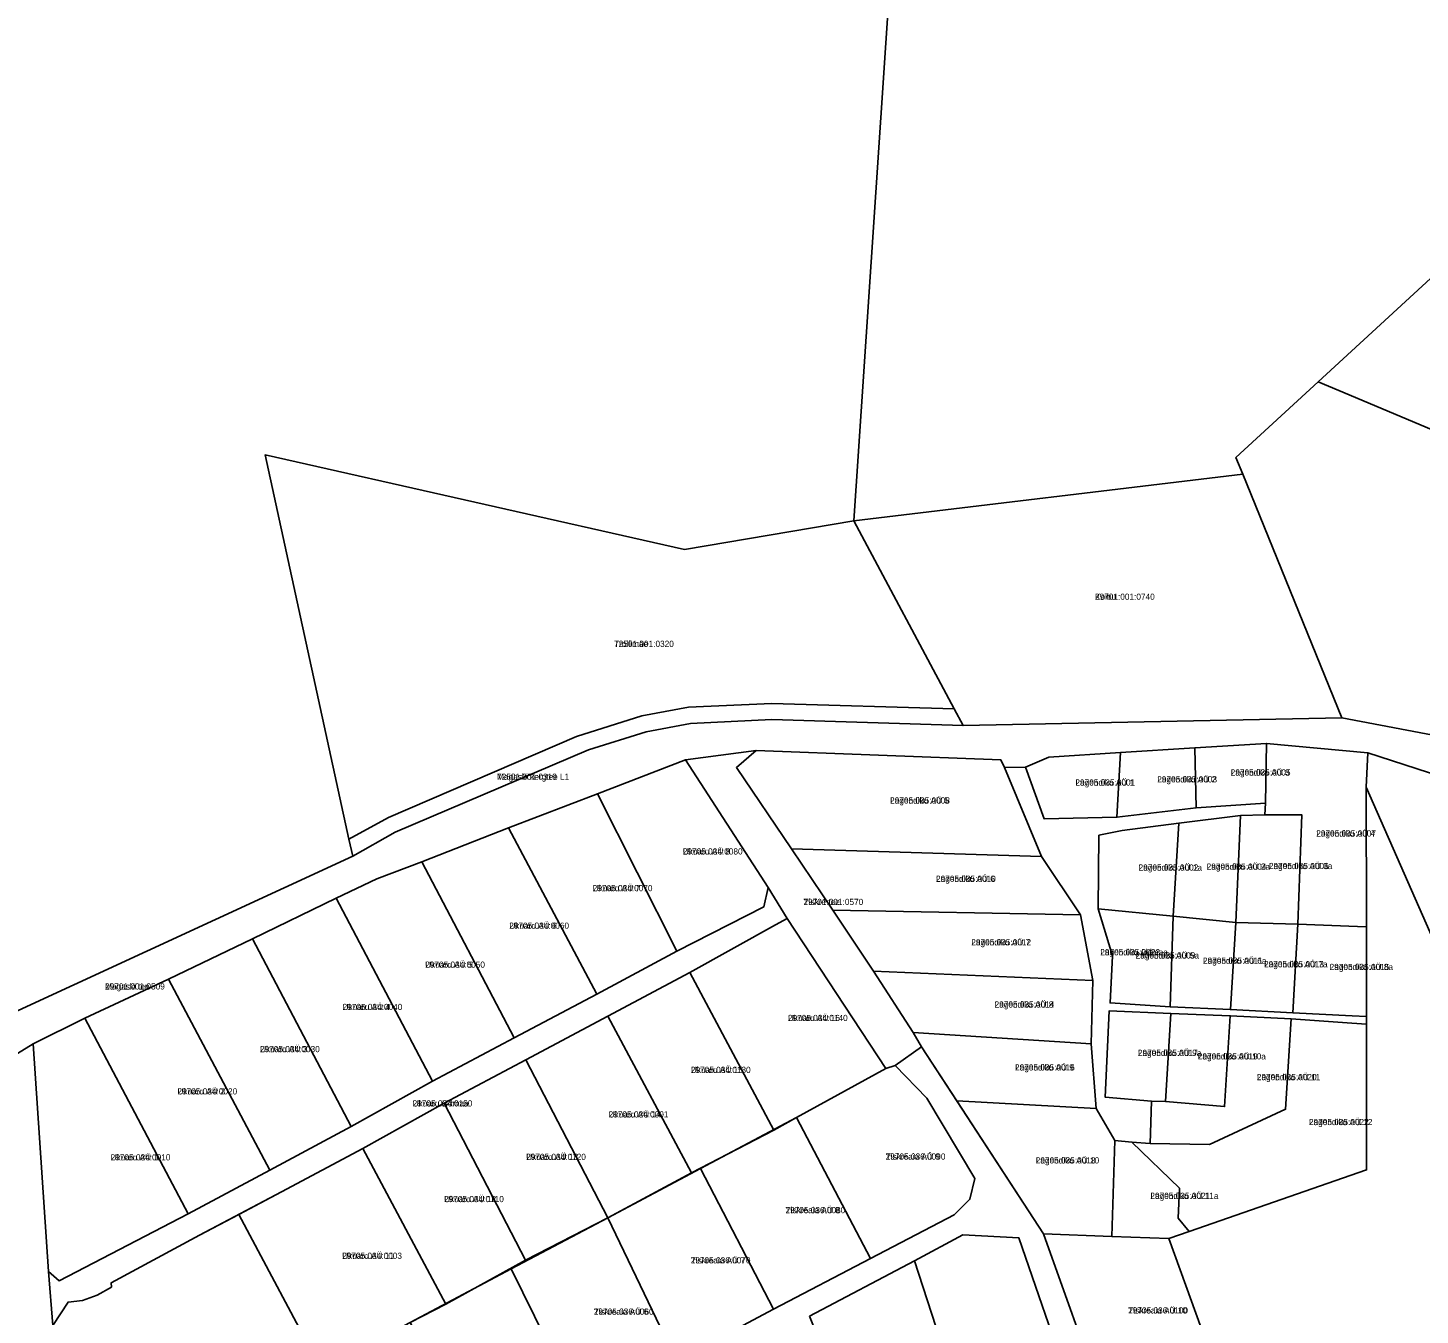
# Model space of a CAD drawing. Extents: x 504287 to 537970, y 6539941 to 6586214.
# Drawn here: x 520266.8 to 520604.6, y 6563598.1 to 6563910.3 of the extents above; entities that cross this region are included whole.
import ezdxf

# ---------------------------------------------------------------- set-up
doc = ezdxf.new("R2010")
doc.units = 0
for name, color, linetype in [('L_AADRESS', 7, 'Continuous'), ('PIIR', 7, 'Continuous'), ('TUNNUS', 7, 'Continuous')]:
    doc.layers.add(name, color=color, linetype=linetype)

msp = doc.modelspace()

# ---------------------------------------------------------------- linework, layer by layer
at = {"layer": 'PIIR'}
for points in [[(520049.76, 6564221.76), (520133.62, 6564211.27), (520351.99, 6564183.27), (520492.24, 6564165.03), (520467.23, 6563790.77), (520426.12, 6563783.83), (520324.37, 6563806.78), (520344.71, 6563713.61), (520345.63, 6563709.46), (520227.9, 6563655.24), (520177.89, 6563631.63), (520169.25, 6563670.06), (520159.84, 6563669.59), (520153.65, 6563692.73), (520146.94, 6563716.94), (520137.46, 6563749.39), (520130.05, 6563775.93), (520115.56, 6563827.84), (520107.48, 6563856.66), (520103.55, 6563870.19), (520064.29, 6563860.64), (520030.28, 6563852.76), (520018.97, 6563851.3)], [(520613.53, 6563810.32), (520584.85, 6563822.37), (520579.85, 6563824.47), (520624.25, 6563865.33), (520634.41, 6563865.62), (520655.2, 6563866.22), (520654.46, 6563829.38), (520627.97, 6563828.87), (520628.39, 6563819.85), (520615.64, 6563819.45)], [(520559.92, 6563806.13), (520579.85, 6563824.47), (520584.85, 6563822.37), (520613.53, 6563810.32), (520615.64, 6563819.45), (520628.39, 6563819.85), (520654.01, 6563820.63), (520650.17, 6563775.76), (520638.69, 6563727.19), (520610.79, 6563738.2), (520585.6, 6563743.01), (520561.6, 6563802.13)], [(520467.23, 6563790.77), (520491.55, 6563745.16), (520447.28, 6563746.5), (520427.09, 6563745.59), (520415.79, 6563743.46), (520399.93, 6563738.5), (520354.28, 6563718.86), (520344.71, 6563713.61), (520324.37, 6563806.78), (520426.12, 6563783.83)], [(520467.23, 6563790.77), (520561.6, 6563802.13), (520585.6, 6563743.01), (520493.72, 6563741.14), (520491.55, 6563745.16)], [(520345.63, 6563709.46), (520344.71, 6563713.61), (520354.28, 6563718.86), (520399.93, 6563738.5), (520415.79, 6563743.46), (520427.09, 6563745.59), (520447.28, 6563746.5), (520491.55, 6563745.16), (520493.72, 6563741.14), (520447.34, 6563742.57), (520427.54, 6563741.61), (520416.83, 6563739.57), (520402.83, 6563735.22), (520355.93, 6563715.26)], [(520549.93, 6563735.76), (520567.35, 6563736.8), (520567.09, 6563722.32), (520550.29, 6563721.21)], [(520567.35, 6563736.8), (520591.89, 6563734.48), (520591.52, 6563726.22), (520591.55, 6563692.35), (520589.39, 6563692.43), (520574.91, 6563692.94), (520575.89, 6563719.5), (520566.89, 6563719.51), (520567.09, 6563722.32)], [(520405.01, 6563724.55), (520426.37, 6563732.81), (520446.43, 6563701.89), (520445.33, 6563697.15), (520424.26, 6563686.42)], [(520446.43, 6563701.89), (520426.37, 6563732.81), (520443.48, 6563735.08), (520438.73, 6563730.94), (520452.07, 6563711.21), (520462.09, 6563696.37), (520472.01, 6563681.55), (520481.56, 6563666.68), (520483.61, 6563663.18), (520477.27, 6563658.68), (520474.98, 6563657.95), (520451.02, 6563694.36)], [(520443.48, 6563735.08), (520502.87, 6563732.78), (520503.77, 6563730.99), (520512.72, 6563709.36), (520452.07, 6563711.21), (520438.73, 6563730.94)], [(520508.89, 6563731.04), (520514.52, 6563733.5), (520531.93, 6563734.62), (520531.02, 6563718.91), (520513.36, 6563718.52)], [(520531.93, 6563734.62), (520549.93, 6563735.76), (520550.29, 6563721.21), (520531.02, 6563718.91)], [(520591.89, 6563734.48), (520630.32, 6563722.1), (520681.93, 6563703.6), (520743.33, 6563677.32), (520827.1, 6563650.11), (520860.34, 6563636.54), (520913.9, 6563618.59), (520690.46, 6563500.96), (520653.9, 6563584.36), (520591.52, 6563726.22)], [(520503.77, 6563730.99), (520508.89, 6563731.04), (520513.36, 6563718.52), (520531.02, 6563718.91), (520550.29, 6563721.21), (520567.09, 6563722.32), (520566.89, 6563719.51), (520560.98, 6563719.35), (520546.09, 6563717.42), (520532.33, 6563715.69), (520526.66, 6563714.54), (520526.49, 6563696.69), (520529.99, 6563685.27), (520529.36, 6563673.88), (520543.93, 6563672.94), (520558.57, 6563672.27), (520573.71, 6563671.47), (520588.08, 6563670.72), (520591.58, 6563670.54), (520591.58, 6563668.72), (520588.02, 6563668.96), (520573.31, 6563670), (520558.53, 6563670.75), (520544.09, 6563671.26), (520529.18, 6563671.97), (520528.15, 6563651.05), (520539.39, 6563650.08), (520539.07, 6563639.79), (520534.66, 6563640.11), (520530.51, 6563640.47), (520525.99, 6563648.28), (520524.8, 6563663.93), (520525.22, 6563679.27), (520522.2, 6563695.24), (520512.72, 6563709.36)], [(520653.9, 6563584.36), (520690.46, 6563500.96), (520766.28, 6563326.22), (520851.17, 6563135.12), (520568.37, 6562931.82), (520394.16, 6563025.62), (520531.01, 6563315.92), (520645.56, 6563341.08), (520574.09, 6563532.77), (520566.89, 6563552.57), (520554.29, 6563587.26), (520543.59, 6563616.74), (520548.53, 6563618.45), (520591.62, 6563633.38), (520591.58, 6563668.72), (520591.58, 6563670.54), (520591.55, 6563692.35), (520591.52, 6563726.22)], [(520383.45, 6563716.34), (520405.01, 6563724.55), (520424.26, 6563686.42), (520404.82, 6563675.99)], [(520546.09, 6563717.42), (520560.98, 6563719.35), (520559.91, 6563693.33), (520544.65, 6563694.88)], [(520560.98, 6563719.35), (520566.89, 6563719.51), (520575.89, 6563719.5), (520574.91, 6563692.94), (520559.91, 6563693.33)], [(520383.45, 6563716.34), (520404.82, 6563675.99), (520384.82, 6563665.38), (520362.41, 6563708.11)], [(520532.33, 6563715.69), (520546.09, 6563717.42), (520544.65, 6563694.88), (520526.49, 6563696.69), (520526.66, 6563714.54)], [(520452.07, 6563711.21), (520512.72, 6563709.36), (520522.2, 6563695.24), (520462.09, 6563696.37)], [(520351.48, 6563703.92), (520362.41, 6563708.11), (520384.82, 6563665.38), (520364.98, 6563654.86), (520341.6, 6563699.3)], [(520328.35, 6563628.05), (520308.44, 6563617.53), (520287.05, 6563605.99), (520287.14, 6563604.95), (520283.6, 6563603.02), (520280.04, 6563601.69), (520276.58, 6563601.31), (520272.89, 6563595.6), (520271.83, 6563608.74), (520274.38, 6563606.49), (520305.73, 6563622.73), (520325.54, 6563633.3), (520345.29, 6563643.91), (520364.98, 6563654.86), (520384.82, 6563665.38), (520404.82, 6563675.99), (520424.26, 6563686.42), (520445.33, 6563697.15), (520446.43, 6563701.89), (520451.02, 6563694.36), (520448.19, 6563692.84), (520427.45, 6563681.26), (520407.54, 6563670.67), (520387.66, 6563660.1), (520367.83, 6563649.57), (520348.07, 6563638.59)], [(520341.6, 6563699.3), (520364.98, 6563654.86), (520345.29, 6563643.91), (520321.34, 6563689.39)], [(520462.09, 6563696.37), (520522.2, 6563695.24), (520525.22, 6563679.27), (520472.01, 6563681.55)], [(520526.49, 6563696.69), (520544.65, 6563694.88), (520543.93, 6563672.94), (520529.36, 6563673.88), (520529.99, 6563685.27)], [(520427.45, 6563681.26), (520448.19, 6563692.84), (520451.02, 6563694.36), (520474.98, 6563657.95), (520453.29, 6563646.05), (520447.8, 6563642.97)], [(520544.65, 6563694.88), (520559.91, 6563693.33), (520558.57, 6563672.27), (520543.93, 6563672.94)], [(520559.91, 6563693.33), (520574.91, 6563692.94), (520573.71, 6563671.47), (520558.57, 6563672.27)], [(520574.91, 6563692.94), (520589.39, 6563692.43), (520591.55, 6563692.35), (520591.58, 6563670.54), (520588.08, 6563670.72), (520573.71, 6563671.47)], [(520321.34, 6563689.39), (520345.29, 6563643.91), (520325.54, 6563633.3), (520300.97, 6563679.66)], [(520300.97, 6563679.66), (520325.54, 6563633.3), (520305.73, 6563622.73), (520280.66, 6563670.17)], [(520427.45, 6563681.26), (520447.8, 6563642.97), (520427.81, 6563632.65), (520407.54, 6563670.67)], [(520472.01, 6563681.55), (520525.22, 6563679.27), (520524.8, 6563663.93), (520481.56, 6563666.68)], [(520529.18, 6563671.97), (520544.09, 6563671.26), (520542.8, 6563649.96), (520539.39, 6563650.08), (520528.15, 6563651.05)], [(520271.83, 6563608.74), (520268.08, 6563663.97), (520280.66, 6563670.17), (520305.73, 6563622.73), (520274.38, 6563606.49)], [(520407.54, 6563670.67), (520427.81, 6563632.65), (520407.56, 6563621.77), (520387.66, 6563660.1)], [(520534.66, 6563640.11), (520539.07, 6563639.79), (520553.47, 6563639.51), (520571.95, 6563648.08), (520573.31, 6563670), (520588.02, 6563668.96), (520591.58, 6563668.72), (520591.62, 6563633.38), (520548.53, 6563618.45), (520545.89, 6563621.67), (520546.24, 6563628.91)], [(520539.39, 6563650.08), (520542.8, 6563649.96), (520557.17, 6563648.74), (520558.53, 6563670.75), (520573.31, 6563670), (520571.95, 6563648.08), (520553.47, 6563639.51), (520539.07, 6563639.79)], [(520544.09, 6563671.26), (520558.53, 6563670.75), (520557.17, 6563648.74), (520542.8, 6563649.96)], [(520481.56, 6563666.68), (520524.8, 6563663.93), (520525.99, 6563648.28), (520492.18, 6563650.09), (520483.61, 6563663.18)], [(520257.63, 6563657.58), (520268.08, 6563663.97), (520271.83, 6563608.74), (520272.89, 6563595.6), (520275.86, 6563552.04), (520272.71, 6563513.64), (520271.28, 6563505.8), (520270.5, 6563484.59), (520270.25, 6563478.62), (520267.25, 6563438.79), (520257.56, 6563438.3), (520260.71, 6563484.77), (520260.51, 6563490.03), (520264.57, 6563548.68)], [(520387.66, 6563660.1), (520407.56, 6563621.77), (520387.54, 6563611.44), (520367.83, 6563649.57)], [(520484.93, 6563650.76), (520496.56, 6563631.27), (520495.36, 6563626.27), (520491.55, 6563622.51), (520471.28, 6563611.89), (520453.29, 6563646.05), (520474.98, 6563657.95), (520477.27, 6563658.68)], [(520348.07, 6563638.59), (520367.83, 6563649.57), (520387.54, 6563611.44), (520368.18, 6563600.83)], [(520492.18, 6563650.09), (520525.99, 6563648.28), (520530.51, 6563640.47), (520529.78, 6563617.25), (520513.26, 6563617.87)], [(520429.98, 6563633.73), (520453.29, 6563646.05), (520471.28, 6563611.89), (520447.71, 6563599.57)], [(520317.96, 6563622.56), (520328.35, 6563628.05), (520348.07, 6563638.59), (520368.18, 6563600.83), (520359.58, 6563596.39), (520348.38, 6563590.49), (520337.98, 6563585.01)], [(520530.51, 6563640.47), (520534.66, 6563640.11), (520546.24, 6563628.91), (520545.89, 6563621.67), (520548.53, 6563618.45), (520543.59, 6563616.74), (520529.78, 6563617.25)], [(520407.56, 6563621.77), (520429.98, 6563633.73), (520447.71, 6563599.57), (520424.16, 6563587.06)], [(520272.89, 6563595.6), (520276.58, 6563601.31), (520280.04, 6563601.69), (520283.6, 6563603.02), (520287.14, 6563604.95), (520287.05, 6563605.99), (520308.44, 6563617.53), (520317.96, 6563622.56), (520337.98, 6563585.01), (520336.23, 6563584.04), (520328.37, 6563579.95), (520312.52, 6563571.44), (520289.75, 6563559.38), (520275.86, 6563552.04)], [(520384.1, 6563609.36), (520407.56, 6563621.77), (520424.16, 6563587.06), (520401.09, 6563574.94)], [(520481.92, 6563611.29), (520493.65, 6563617.6), (520507.25, 6563616.89), (520519.29, 6563581.98), (520494.41, 6563573.02)], [(520513.26, 6563617.87), (520529.78, 6563617.25), (520543.59, 6563616.74), (520554.29, 6563587.26), (520527.51, 6563577.77)], [(520456.44, 6563597.87), (520481.92, 6563611.29), (520494.41, 6563573.02), (520470.02, 6563564.01)], [(520359.58, 6563596.39), (520384.1, 6563609.36), (520401.09, 6563574.94), (520377.85, 6563562.55)]]:
    msp.add_lwpolyline(points, close=True, dxfattribs=at)
for points in [[(520722.24, 6563951.9), (520624.25, 6563865.33), (520579.85, 6563824.47), (520559.92, 6563806.13), (520561.6, 6563802.13), (520467.23, 6563790.77), (520492.24, 6564165.03)], [(520227.9, 6563655.24), (520345.63, 6563709.46), (520355.93, 6563715.26), (520402.83, 6563735.22), (520416.83, 6563739.57), (520427.54, 6563741.61), (520447.34, 6563742.57), (520493.72, 6563741.14), (520585.6, 6563743.01), (520610.79, 6563738.2), (520638.69, 6563727.19), (520672.25, 6563715.51), (520709.6, 6563699.46), (520744.69, 6563685.18), (520758.24, 6563680.87), (520780.44, 6563673.8), (520792.4, 6563669.88), (520795.27, 6563668.99), (520831.46, 6563657.45), (520865.59, 6563643.7), (520916.73, 6563628.95), (520961.55, 6563600.95)], [(520630.32, 6563722.1), (520591.89, 6563734.48), (520567.35, 6563736.8), (520549.93, 6563735.76), (520531.93, 6563734.62), (520514.52, 6563733.5), (520508.89, 6563731.04), (520503.77, 6563730.99), (520502.87, 6563732.78), (520443.48, 6563735.08), (520426.37, 6563732.81), (520405.01, 6563724.55), (520383.45, 6563716.34), (520362.41, 6563708.11), (520351.48, 6563703.92), (520341.6, 6563699.3), (520321.34, 6563689.39), (520300.97, 6563679.66), (520280.66, 6563670.17), (520268.08, 6563663.97), (520257.63, 6563657.58)], [(520424.16, 6563587.06), (520447.71, 6563599.57), (520471.28, 6563611.89), (520491.55, 6563622.51), (520495.36, 6563626.27), (520496.56, 6563631.27), (520484.93, 6563650.76), (520477.27, 6563658.68), (520483.61, 6563663.18), (520513.26, 6563617.87), (520527.51, 6563577.77)], [(520519.29, 6563581.98), (520507.25, 6563616.89), (520493.65, 6563617.6), (520481.92, 6563611.29), (520456.44, 6563597.87)]]:
    msp.add_lwpolyline(points, dxfattribs=at)

# ---------------------------------------------------------------- texts
at = {"layer": 'L_AADRESS'}
for s, p in [('Koibu', (520525.71, 6563771.63)), ('Trollimäe', (520409.04, 6563760.2)), ('Magaski kergtee L1', (520380.65, 6563727.98)), ('Lagendiku AÜ 3', (520558.65, 6563729.01)), ('Lagendiku AÜ 1', (520520.97, 6563726.57)), ('Lagendiku AÜ 2', (520540.82, 6563727.34)), ('Lagendiku AÜ 5', (520476.01, 6563722.22)), ('Lagendiku AÜ 4', (520579.39, 6563714.22)), ('Ukuaru AÜ 8', (520425.72, 6563709.86)), ('Lagendiku AÜ 1a', (520536.29, 6563705.95)), ('Lagendiku AÜ 2a', (520552.81, 6563706.17)), ('Lagendiku AÜ 3a', (520567.9, 6563706.32)), ('Ukuaru AÜ 7', (520403.86, 6563700.96)), ('Lagendiku AÜ 6', (520487.15, 6563703.23)), ('Tiskre tee', (520454.99, 6563697.61)), ('Ukuaru AÜ 6', (520383.61, 6563691.85)), ('Lagendiku AÜ 7', (520495.71, 6563687.82)), ('Lagendiku üldmaa', (520527, 6563685.41)), ('Lagendiku AÜ 5a', (520535.57, 6563684.63)), ('Ukuaru AÜ 5', (520363.21, 6563682.4)), ('Lagendiku AÜ 6a', (520551.92, 6563683.36)), ('Lagendiku AÜ 7a', (520566.74, 6563682.5)), ('Lagendiku AÜ 8a', (520582.64, 6563681.84)), ('Magaski tee', (520285.54, 6563677.12)), ('Ukuaru AÜ 4', (520343.16, 6563672.14)), ('Lagendiku AÜ 8', (520501.35, 6563672.74)), ('Ukuaru AÜ 16', (520451.21, 6563669.47)), ('Ukuaru AÜ 3', (520323.13, 6563661.92)), ('Lagendiku AÜ 9a', (520536.12, 6563661)), ('Lagendiku AÜ 10a', (520550.66, 6563660.16)), ('Ukuaru AÜ 15', (520427.67, 6563656.88)), ('Lagendiku AÜ 9', (520506.32, 6563657.48)), ('Lagendiku AÜ 11', (520564.98, 6563655.13)), ('Ukuaru AÜ 2', (520303.1, 6563651.67)), ('Ukuaru üldmaa', (520360.16, 6563648.75)), ('Ukuaru AÜ 14', (520407.73, 6563646.08)), ('Lagendiku AÜ 12', (520577.62, 6563644.23)), ('Ukuaru AÜ 1', (520286.9, 6563635.67)), ('Ukuaru AÜ 13', (520387.7, 6563635.78)), ('Tiskreaia AÜ 9', (520474.93, 6563635.86)), ('Lagendiku AÜ 10', (520511.34, 6563634.93)), ('Lagendiku AÜ 11a', (520539.16, 6563626.33)), ('Ukuaru AÜ 12', (520367.8, 6563625.55)), ('Tiskreaia AÜ 8', (520450.63, 6563622.87)), ('Ukuaru AÜ 11', (520343.07, 6563611.8)), ('Tiskreaia AÜ 7', (520427.64, 6563610.69)), ('Tiskreaia AÜ 6', (520404.13, 6563598.25)), ('Tiskreaia AÜ 10', (520533.77, 6563598.55))]:
    msp.add_text(s, height=1.5, dxfattribs=at).set_placement(p)
at = {"layer": 'TUNNUS'}
for s, p in [('29701:001:0740', (520525.71, 6563771.63)), ('72501:001:0320', (520409.04, 6563760.2)), ('72501:001:0319', (520380.65, 6563727.98)), ('29705:035:0005', (520558.65, 6563729.01)), ('29705:035:0001', (520520.97, 6563726.57)), ('29705:035:0003', (520540.82, 6563727.34)), ('29705:035:0008', (520476.01, 6563722.22)), ('29705:035:0007', (520579.39, 6563714.22)), ('29705:034:0080', (520425.72, 6563709.86)), ('29705:035:0002', (520536.29, 6563705.95)), ('29705:035:0004', (520552.81, 6563706.17)), ('29705:035:0006', (520567.9, 6563706.32)), ('29705:034:0070', (520403.86, 6563700.96)), ('29705:035:0010', (520487.15, 6563703.23)), ('29701:001:0570', (520454.99, 6563697.61)), ('29705:034:0060', (520383.61, 6563691.85)), ('29705:035:0012', (520495.71, 6563687.82)), ('29705:035:0023', (520527, 6563685.41)), ('29705:035:0009', (520535.57, 6563684.63)), ('29705:034:0050', (520363.21, 6563682.4)), ('29705:035:0011', (520551.92, 6563683.36)), ('29705:035:0013', (520566.74, 6563682.5)), ('29705:035:0015', (520582.64, 6563681.84)), ('29701:001:0509', (520285.54, 6563677.12)), ('29705:034:0040', (520343.16, 6563672.14)), ('29705:035:0014', (520501.35, 6563672.74)), ('29705:034:0140', (520451.21, 6563669.47)), ('29705:034:0030', (520323.13, 6563661.92)), ('29705:035:0017', (520536.12, 6563661)), ('29705:035:0016', (520506.32, 6563657.48)), ('29705:035:0019', (520550.66, 6563660.16)), ('29705:034:0130', (520427.67, 6563656.88)), ('29705:035:0020', (520564.98, 6563655.13)), ('29705:034:0020', (520303.1, 6563651.67)), ('29705:034:0150', (520360.16, 6563648.75)), ('29705:034:0001', (520407.73, 6563646.08)), ('29705:035:0022', (520577.62, 6563644.23)), ('29705:034:0010', (520286.9, 6563635.67)), ('29705:034:0120', (520387.7, 6563635.78)), ('29705:036:0090', (520474.93, 6563635.86)), ('29705:035:0018', (520511.34, 6563634.93)), ('29705:034:0110', (520367.8, 6563625.55)), ('29705:035:0021', (520539.16, 6563626.33)), ('29705:036:0080', (520450.63, 6563622.87)), ('29705:034:0003', (520343.07, 6563611.8)), ('29705:036:0070', (520427.64, 6563610.69)), ('29705:036:0060', (520404.13, 6563598.25)), ('29705:036:0100', (520533.77, 6563598.55))]:
    msp.add_text(s, height=1.5, dxfattribs=at).set_placement(p)

doc.saveas('drawing.dxf')
